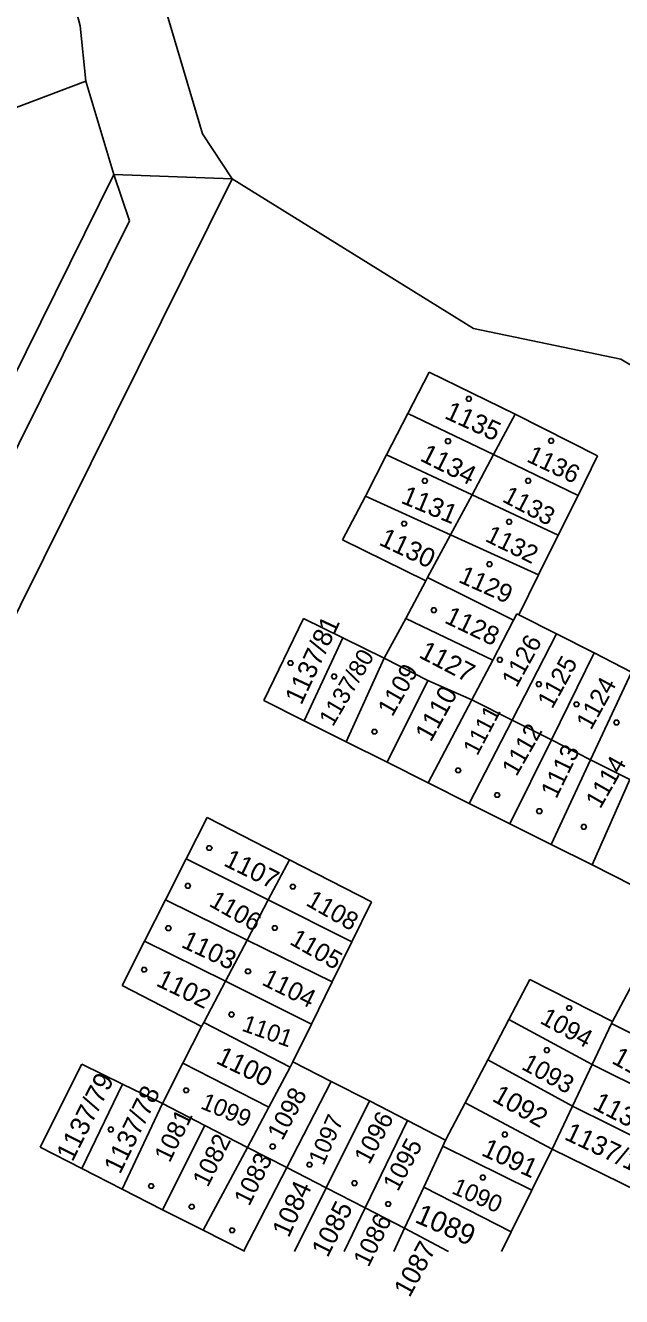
# Model space of a CAD drawing. Extents: x -621797 to -620972, y -1175539 to -1174697.
# Drawn here: x -621447.7 to -621408.1, y -1175535.9 to -1175451.4 of the extents above; entities that cross this region are included whole.
import ezdxf

# ---------------------------------------------------------------- set-up
doc = ezdxf.new("R2010")
doc.units = 0
for name, color, linetype in [('Rozvod plynu EON', 7, 'Continuous'), ('SDEL EON - popis', 7, 'Continuous'), ('Silnoproud EON', 7, 'Continuous'), ('Silnoproud EON - popis', 7, 'Continuous')]:
    doc.layers.add(name, color=color, linetype=linetype)

msp = doc.modelspace()

# ---------------------------------------------------------------- linework, layer by layer
at = {"layer": 'Rozvod plynu EON'}
for points in [[(-621418.2, -1175476.07), (-621418.11, -1175476.22), (-621418.2, -1175476.37), (-621418.38, -1175476.37), (-621418.47, -1175476.22), (-621418.38, -1175476.07)], [(-621419.58, -1175478.88), (-621419.49, -1175479.03), (-621419.58, -1175479.18), (-621419.76, -1175479.18), (-621419.85, -1175479.03), (-621419.76, -1175478.88)], [(-621412.73, -1175478.86), (-621412.64, -1175479.01), (-621412.73, -1175479.16), (-621412.91, -1175479.16), (-621413, -1175479.01), (-621412.91, -1175478.86)], [(-621421.12, -1175481.52), (-621421.03, -1175481.67), (-621421.12, -1175481.82), (-621421.3, -1175481.82), (-621421.39, -1175481.67), (-621421.3, -1175481.52)], [(-621414.26, -1175481.52), (-621414.17, -1175481.67), (-621414.26, -1175481.82), (-621414.44, -1175481.82), (-621414.53, -1175481.67), (-621414.44, -1175481.52)], [(-621415.52, -1175484.24), (-621415.43, -1175484.39), (-621415.52, -1175484.54), (-621415.7, -1175484.54), (-621415.79, -1175484.39), (-621415.7, -1175484.24)], [(-621422.5, -1175484.36), (-621422.41, -1175484.51), (-621422.5, -1175484.66), (-621422.68, -1175484.66), (-621422.77, -1175484.51), (-621422.68, -1175484.36)], [(-621416.83, -1175487.06), (-621416.74, -1175487.21), (-621416.83, -1175487.36), (-621417.01, -1175487.36), (-621417.1, -1175487.21), (-621417.01, -1175487.06)], [(-621420.52, -1175490.11), (-621420.43, -1175490.26), (-621420.52, -1175490.41), (-621420.7, -1175490.41), (-621420.79, -1175490.26), (-621420.7, -1175490.11)], [(-621430.04, -1175493.62), (-621429.95, -1175493.77), (-621430.04, -1175493.92), (-621430.22, -1175493.92), (-621430.31, -1175493.77), (-621430.22, -1175493.62)], [(-621416.13, -1175493.41), (-621416.04, -1175493.56), (-621416.13, -1175493.71), (-621416.31, -1175493.71), (-621416.4, -1175493.56), (-621416.31, -1175493.41)], [(-621427.15, -1175494.52), (-621427.06, -1175494.67), (-621427.15, -1175494.82), (-621427.33, -1175494.82), (-621427.42, -1175494.67), (-621427.33, -1175494.52)], [(-621413.55, -1175495.03), (-621413.46, -1175495.18), (-621413.55, -1175495.33), (-621413.73, -1175495.33), (-621413.82, -1175495.18), (-621413.73, -1175495.03)], [(-621411.04, -1175496.36), (-621410.95, -1175496.51), (-621411.04, -1175496.66), (-621411.22, -1175496.66), (-621411.31, -1175496.51), (-621411.22, -1175496.36)], [(-621408.39, -1175497.57), (-621408.3, -1175497.72), (-621408.39, -1175497.87), (-621408.57, -1175497.87), (-621408.66, -1175497.72), (-621408.57, -1175497.57)], [(-621424.47, -1175498.18), (-621424.38, -1175498.33), (-621424.47, -1175498.48), (-621424.65, -1175498.48), (-621424.74, -1175498.33), (-621424.65, -1175498.18)], [(-621418.9, -1175500.75), (-621418.81, -1175500.9), (-621418.9, -1175501.05), (-621419.08, -1175501.05), (-621419.17, -1175500.9), (-621419.08, -1175500.75)], [(-621416.31, -1175502.39), (-621416.22, -1175502.54), (-621416.31, -1175502.69), (-621416.49, -1175502.69), (-621416.58, -1175502.54), (-621416.49, -1175502.39)], [(-621413.51, -1175503.46), (-621413.42, -1175503.61), (-621413.51, -1175503.76), (-621413.69, -1175503.76), (-621413.78, -1175503.61), (-621413.69, -1175503.46)], [(-621410.56, -1175504.5), (-621410.47, -1175504.65), (-621410.56, -1175504.8), (-621410.74, -1175504.8), (-621410.83, -1175504.65), (-621410.74, -1175504.5)], [(-621435.44, -1175505.91), (-621435.35, -1175506.06), (-621435.44, -1175506.21), (-621435.62, -1175506.21), (-621435.71, -1175506.06), (-621435.62, -1175505.91)], [(-621436.86, -1175508.42), (-621436.77, -1175508.57), (-621436.86, -1175508.72), (-621437.04, -1175508.72), (-621437.13, -1175508.57), (-621437.04, -1175508.42)], [(-621429.89, -1175508.47), (-621429.8, -1175508.62), (-621429.89, -1175508.77), (-621430.07, -1175508.77), (-621430.16, -1175508.62), (-621430.07, -1175508.47)], [(-621438.16, -1175511.23), (-621438.07, -1175511.38), (-621438.16, -1175511.53), (-621438.34, -1175511.53), (-621438.43, -1175511.38), (-621438.34, -1175511.23)], [(-621431.09, -1175511.22), (-621431, -1175511.37), (-621431.09, -1175511.52), (-621431.27, -1175511.52), (-621431.36, -1175511.37), (-621431.27, -1175511.22)], [(-621439.77, -1175513.99), (-621439.68, -1175514.14), (-621439.77, -1175514.29), (-621439.95, -1175514.29), (-621440.04, -1175514.14), (-621439.95, -1175513.99)], [(-621432.87, -1175514.1), (-621432.78, -1175514.25), (-621432.87, -1175514.4), (-621433.05, -1175514.4), (-621433.14, -1175514.25), (-621433.05, -1175514.1)], [(-621433.96, -1175516.96), (-621433.87, -1175517.11), (-621433.96, -1175517.26), (-621434.14, -1175517.26), (-621434.23, -1175517.11), (-621434.14, -1175516.96)], [(-621411.52, -1175516.53), (-621411.43, -1175516.68), (-621411.52, -1175516.83), (-621411.7, -1175516.83), (-621411.79, -1175516.68), (-621411.7, -1175516.53)], [(-621413.01, -1175519.33), (-621412.92, -1175519.48), (-621413.01, -1175519.63), (-621413.19, -1175519.63), (-621413.28, -1175519.48), (-621413.19, -1175519.33)], [(-621436.98, -1175522), (-621436.89, -1175522.15), (-621436.98, -1175522.3), (-621437.16, -1175522.3), (-621437.25, -1175522.15), (-621437.16, -1175522)], [(-621441.99, -1175524.61), (-621441.9, -1175524.76), (-621441.99, -1175524.91), (-621442.17, -1175524.91), (-621442.26, -1175524.76), (-621442.17, -1175524.61)], [(-621415.81, -1175524.93), (-621415.72, -1175525.08), (-621415.81, -1175525.23), (-621415.99, -1175525.23), (-621416.08, -1175525.08), (-621415.99, -1175524.93)], [(-621431.23, -1175525.73), (-621431.14, -1175525.88), (-621431.23, -1175526.03), (-621431.41, -1175526.03), (-621431.5, -1175525.88), (-621431.41, -1175525.73)], [(-621428.78, -1175526.94), (-621428.69, -1175527.09), (-621428.78, -1175527.24), (-621428.96, -1175527.24), (-621429.05, -1175527.09), (-621428.96, -1175526.94)], [(-621425.8, -1175528.17), (-621425.71, -1175528.32), (-621425.8, -1175528.47), (-621425.98, -1175528.47), (-621426.07, -1175528.32), (-621425.98, -1175528.17)], [(-621417.26, -1175527.79), (-621417.17, -1175527.94), (-621417.26, -1175528.09), (-621417.44, -1175528.09), (-621417.53, -1175527.94), (-621417.44, -1175527.79)], [(-621439.3, -1175528.36), (-621439.21, -1175528.51), (-621439.3, -1175528.66), (-621439.48, -1175528.66), (-621439.57, -1175528.51), (-621439.48, -1175528.36)], [(-621436.61, -1175529.73), (-621436.52, -1175529.88), (-621436.61, -1175530.03), (-621436.79, -1175530.03), (-621436.88, -1175529.88), (-621436.79, -1175529.73)], [(-621423.55, -1175529.55), (-621423.46, -1175529.7), (-621423.55, -1175529.85), (-621423.73, -1175529.85), (-621423.82, -1175529.7), (-621423.73, -1175529.55)], [(-621433.92, -1175531.3), (-621433.83, -1175531.45), (-621433.92, -1175531.6), (-621434.1, -1175531.6), (-621434.19, -1175531.45), (-621434.1, -1175531.3)]]:
    msp.add_lwpolyline(points, close=True, dxfattribs=at)
at = {"layer": 'SDEL EON - popis'}
for p, q in [((-621440.83, -1175464.39), (-621441.87, -1175461.33)), ((-621474.84, -1175532.85), (-621440.83, -1175464.39))]:
    msp.add_line(p, q, dxfattribs=at)
at = {"layer": 'Silnoproud EON'}
for p, q in [((-621441.44, -1175440.21), (-621435.99, -1175458.63)), ((-621444.1, -1175451.45), (-621446.68, -1175441.99)), ((-621443.74, -1175455.13), (-621444.1, -1175451.45)), ((-621462.68, -1175462.26), (-621443.74, -1175455.13)), ((-621443.74, -1175455.13), (-621441.87, -1175461.33)), ((-621435.99, -1175458.63), (-621434.02, -1175461.6)), ((-621449.7, -1175477.12), (-621441.87, -1175461.33)), ((-621441.87, -1175461.33), (-621434.02, -1175461.6)), ((-621434.02, -1175461.6), (-621469.406, -1175532.85)), ((-621417.98, -1175471.56), (-621434.02, -1175461.6)), ((-621408.19, -1175473.58), (-621417.98, -1175471.56)), ((-621399.98, -1175478.5), (-621408.19, -1175473.58)), ((-621422.33, -1175477.19), (-621420.91, -1175474.45)), ((-621420.91, -1175474.45), (-621415.2, -1175477.25)), ((-621423.75, -1175479.94), (-621422.33, -1175477.19)), ((-621422.33, -1175477.19), (-621416.64, -1175479.93)), ((-621415.2, -1175477.25), (-621416.64, -1175479.93)), ((-621415.2, -1175477.25), (-621409.73, -1175480)), ((-621425.16, -1175482.68), (-621423.75, -1175479.94)), ((-621423.75, -1175479.94), (-621418.07, -1175482.6)), ((-621416.64, -1175479.93), (-621418.07, -1175482.6)), ((-621416.64, -1175479.93), (-621411.03, -1175482.64)), ((-621409.73, -1175480), (-621411.03, -1175482.64)), ((-621418.07, -1175482.6), (-621419.5, -1175485.26)), ((-621418.07, -1175482.6), (-621412.34, -1175485.28)), ((-621411.03, -1175482.64), (-621412.34, -1175485.28)), ((-621426.67, -1175485.59), (-621425.16, -1175482.68)), ((-621425.16, -1175482.68), (-621419.5, -1175485.26)), ((-621421.14, -1175488.3), (-621426.67, -1175485.59)), ((-621419.5, -1175485.26), (-621421.03, -1175488.1)), ((-621419.5, -1175485.26), (-621413.65, -1175487.92)), ((-621412.34, -1175485.28), (-621413.65, -1175487.92)), ((-621422.48, -1175490.81), (-621421.14, -1175488.3)), ((-621421.03, -1175488.1), (-621421.14, -1175488.3)), ((-621421.03, -1175488.1), (-621415.31, -1175490.92)), ((-621413.65, -1175487.92), (-621414.96, -1175490.57)), ((-621431.91, -1175496.26), (-621429.26, -1175490.82)), ((-621429.26, -1175490.82), (-621426.66, -1175492.1)), ((-621423.9, -1175493.45), (-621422.48, -1175490.81)), ((-621422.48, -1175490.81), (-621416.7, -1175493.57)), ((-621415.31, -1175490.92), (-621416.7, -1175493.57)), ((-621415.09, -1175490.5), (-621415.31, -1175490.92)), ((-621414.96, -1175490.57), (-621415.09, -1175490.5)), ((-621414.96, -1175490.57), (-621412.46, -1175491.84)), ((-621412.46, -1175491.84), (-621415.41, -1175497.56)), ((-621412.46, -1175491.84), (-621409.96, -1175493.1)), ((-621426.66, -1175492.1), (-621429.22, -1175497.61)), ((-621426.66, -1175492.1), (-621423.9, -1175493.45)), ((-621423.9, -1175493.45), (-621426.44, -1175499)), ((-621423.9, -1175493.45), (-621421.01, -1175494.94)), ((-621416.7, -1175493.57), (-621418.09, -1175496.21)), ((-621409.96, -1175493.1), (-621412.8, -1175498.87)), ((-621409.96, -1175493.1), (-621407.47, -1175494.37)), ((-621407.47, -1175494.37), (-621410.19, -1175500.19)), ((-621421.01, -1175494.94), (-621423.72, -1175500.36)), ((-621421.01, -1175494.94), (-621418.09, -1175496.21)), ((-621429.22, -1175497.61), (-621431.91, -1175496.26)), ((-621418.09, -1175496.21), (-621420.99, -1175501.73)), ((-621418.09, -1175496.21), (-621415.41, -1175497.56)), ((-621426.44, -1175499), (-621429.22, -1175497.61)), ((-621415.41, -1175497.56), (-621418.26, -1175503.09)), ((-621415.41, -1175497.56), (-621412.8, -1175498.87)), ((-621423.72, -1175500.36), (-621426.44, -1175499)), ((-621412.8, -1175498.87), (-621415.55, -1175504.45)), ((-621412.8, -1175498.87), (-621410.19, -1175500.19)), ((-621420.99, -1175501.73), (-621423.72, -1175500.36)), ((-621410.19, -1175500.19), (-621412.82, -1175505.82)), ((-621410.19, -1175500.19), (-621407.58, -1175501.5)), ((-621418.26, -1175503.09), (-621420.99, -1175501.73)), ((-621407.58, -1175501.5), (-621410.1, -1175507.18)), ((-621415.55, -1175504.45), (-621418.26, -1175503.09)), ((-621435.68, -1175504.03), (-621437.07, -1175506.77)), ((-621430.21, -1175506.84), (-621435.68, -1175504.03)), ((-621412.82, -1175505.82), (-621415.55, -1175504.45)), ((-621410.1, -1175507.18), (-621412.82, -1175505.82)), ((-621437.07, -1175506.77), (-621438.45, -1175509.5)), ((-621437.07, -1175506.77), (-621431.61, -1175509.51)), ((-621430.21, -1175506.84), (-621431.61, -1175509.51)), ((-621424.75, -1175509.64), (-621430.21, -1175506.84)), ((-621407.39, -1175508.54), (-621410.1, -1175507.18)), ((-621438.45, -1175509.5), (-621439.83, -1175512.24)), ((-621438.45, -1175509.5), (-621433.01, -1175512.17)), ((-621431.61, -1175509.51), (-621433.01, -1175512.17)), ((-621431.61, -1175509.51), (-621426.06, -1175512.3)), ((-621426.06, -1175512.3), (-621424.75, -1175509.64)), ((-621433.01, -1175512.17), (-621434.46, -1175514.91)), ((-621433.01, -1175512.17), (-621427.36, -1175514.95)), ((-621439.83, -1175512.24), (-621441.33, -1175515.19)), ((-621439.83, -1175512.24), (-621434.46, -1175514.91)), ((-621427.36, -1175514.95), (-621426.06, -1175512.3)), ((-621441.33, -1175515.19), (-621436.04, -1175517.92)), ((-621434.46, -1175514.91), (-621435.9, -1175517.65)), ((-621434.46, -1175514.91), (-621428.74, -1175517.76)), ((-621428.74, -1175517.76), (-621427.36, -1175514.95)), ((-621414.23, -1175514.78), (-621415.63, -1175517.45)), ((-621408.74, -1175517.59), (-621414.23, -1175514.78)), ((-621407.44, -1175515.12), (-621408.74, -1175517.59)), ((-621436.04, -1175517.92), (-621437.28, -1175520.35)), ((-621435.9, -1175517.65), (-621436.04, -1175517.92)), ((-621435.9, -1175517.65), (-621430.16, -1175520.61)), ((-621429.97, -1175520.25), (-621428.74, -1175517.76)), ((-621415.63, -1175517.45), (-621417.03, -1175520.13)), ((-621415.63, -1175517.45), (-621410.09, -1175520.44)), ((-621410.09, -1175520.44), (-621408.8, -1175517.71)), ((-621408.8, -1175517.71), (-621408.74, -1175517.59)), ((-621408.8, -1175517.71), (-621402.93, -1175520.64)), ((-621444.01, -1175520.42), (-621446.77, -1175525.93)), ((-621441.29, -1175521.74), (-621444.01, -1175520.42)), ((-621437.28, -1175520.35), (-621438.65, -1175523.02)), ((-621437.28, -1175520.35), (-621431.58, -1175523.28)), ((-621430.16, -1175520.61), (-621431.58, -1175523.28)), ((-621429.97, -1175520.25), (-621430.16, -1175520.61)), ((-621427.43, -1175521.56), (-621429.97, -1175520.25)), ((-621417.03, -1175520.13), (-621418.52, -1175522.99)), ((-621417.03, -1175520.13), (-621411.4, -1175523.2)), ((-621411.4, -1175523.2), (-621410.09, -1175520.44)), ((-621410.09, -1175520.44), (-621404.29, -1175523.33)), ((-621441.29, -1175521.74), (-621443.99, -1175527.35)), ((-621438.65, -1175523.02), (-621441.29, -1175521.74)), ((-621427.43, -1175521.56), (-621430.38, -1175527.28)), ((-621424.89, -1175522.86), (-621427.43, -1175521.56)), ((-621438.65, -1175523.02), (-621441.32, -1175528.71)), ((-621438.65, -1175523.02), (-621435.83, -1175524.49)), ((-621424.89, -1175522.86), (-621427.76, -1175528.62)), ((-621422.36, -1175524.16), (-621424.89, -1175522.86)), ((-621418.52, -1175522.99), (-621419.83, -1175525.46)), ((-621418.52, -1175522.99), (-621412.75, -1175526.06)), ((-621431.58, -1175523.28), (-621433, -1175525.94)), ((-621412.75, -1175526.06), (-621411.4, -1175523.2)), ((-621411.4, -1175523.2), (-621405.66, -1175526.06)), ((-621435.83, -1175524.49), (-621438.63, -1175530.08)), ((-621435.83, -1175524.49), (-621433, -1175525.94)), ((-621422.36, -1175524.16), (-621425.17, -1175529.96)), ((-621419.83, -1175525.46), (-621422.36, -1175524.16)), ((-621419.83, -1175525.46), (-621420.01, -1175525.86)), ((-621446.77, -1175525.93), (-621443.99, -1175527.35)), ((-621433, -1175525.94), (-621435.93, -1175531.45)), ((-621433, -1175525.94), (-621430.38, -1175527.28)), ((-621420.01, -1175525.86), (-621421.28, -1175528.58)), ((-621420.01, -1175525.86), (-621414.1, -1175528.78)), ((-621414.1, -1175528.78), (-621412.75, -1175526.06)), ((-621412.75, -1175526.06), (-621407.06, -1175528.85)), ((-621443.99, -1175527.35), (-621441.32, -1175528.71)), ((-621430.38, -1175527.28), (-621433.24, -1175532.82)), ((-621430.38, -1175527.28), (-621427.76, -1175528.62)), ((-621441.32, -1175528.71), (-621438.63, -1175530.08)), ((-621427.76, -1175528.62), (-621429.867, -1175532.85)), ((-621427.76, -1175528.62), (-621425.17, -1175529.96)), ((-621421.28, -1175528.58), (-621422.55, -1175531.3)), ((-621421.28, -1175528.58), (-621415.48, -1175531.56)), ((-621415.48, -1175531.56), (-621414.1, -1175528.78)), ((-621438.63, -1175530.08), (-621435.93, -1175531.45)), ((-621425.17, -1175529.96), (-621426.571, -1175532.85)), ((-621425.17, -1175529.96), (-621422.55, -1175531.3)), ((-621435.93, -1175531.45), (-621433.24, -1175532.82)), ((-621422.55, -1175531.3), (-621423.274, -1175532.85)), ((-621422.55, -1175531.3), (-621419.72, -1175532.81)), ((-621416.122, -1175532.85), (-621415.48, -1175531.56)), ((-621433.24, -1175532.82), (-621433.181, -1175532.85)), ((-621419.72, -1175532.81), (-621419.74, -1175532.85)), ((-621419.72, -1175532.81), (-621419.646, -1175532.85))]:
    msp.add_line(p, q, dxfattribs=at)

# ---------------------------------------------------------------- texts
at = {"layer": 'Silnoproud EON - popis'}
for s, height, rotation, p in [('1135', 1.27, 335.2949, (-621419.973, -1175477.483)), ('1134', 1.27, 333.34684, (-621421.598, -1175480.292)), ('1136', 1.2, 334.77924, (-621414.509, -1175480.358)), ('1131', 1.27, 337.41484, (-621422.869, -1175483.113)), ('1133', 1.2, 332.08634, (-621416.135, -1175483.01)), ('1130', 1.27, 334.49276, (-621424.325, -1175485.886)), ('1132', 1.2, 333.9198, (-621417.271, -1175485.642)), ('1129', 1.22, 336.03975, (-621419.045, -1175488.371)), ('1128', 1.24, 334.37817, (-621419.972, -1175491.066)), ('1137/81', 1.27, 64.97341, (-621429.416, -1175496.614)), ('1126', 1.2, 61.19189, (-621415.116, -1175495.457)), ('1127', 1.27, 332.43011, (-621421.672, -1175493.365)), ('1137/80', 1.14, 59.58761, (-621427.321, -1175498.048)), ('1125', 1.2, 61.19189, (-621412.746, -1175496.867)), ('1109', 1.2, 60.27516, (-621423.373, -1175497.389)), ('1124', 1.2, 61.19189, (-621410.166, -1175498.277)), ('1110', 1.27, 61.1346, (-621420.816, -1175499.074)), ('1111', 1.14, 62.16592, (-621417.722, -1175499.982)), ('1112', 1.2, 60.27516, (-621415.123, -1175501.359)), ('1113', 1.22, 64.05668, (-621412.469, -1175502.838)), ('1114', 1.2, 60.27516, (-621409.553, -1175503.509)), ('1107', 1.25, 333.9771, (-621434.648, -1175507.196)), ('1106', 1.2, 330.31017, (-621435.619, -1175509.867)), ('1108', 1.2, 330.31017, (-621429.179, -1175509.827)), ('1103', 1.24, 334.83654, (-621437.461, -1175512.611)), ('1105', 1.2, 330.31017, (-621430.259, -1175512.407)), ('1102', 1.24, 334.20628, (-621439.135, -1175515.17)), ('1104', 1.22, 333.63333, (-621432.109, -1175515.111)), ('1101', 1.14, 340.45152, (-621433.438, -1175518.175)), ('1094', 1.2, 331.2269, (-621413.627, -1175517.653)), ('1100', 1.27, 334.14899, (-621435.155, -1175520.318)), ('1137/13', 1.27, 331.34149, (-621408.863, -1175520.311)), ('1093', 1.2, 331.2269, (-621414.857, -1175520.703)), ('1137/79', 1.28, 63.19724, (-621444.62, -1175526.95)), ('1137/78', 1.27, 63.99939, (-621441.461, -1175527.776)), ('1098', 1.2, 62.10862, (-621430.68, -1175525.545)), ('1092', 1.27, 330.53935, (-621416.808, -1175522.82)), ('1099', 1.14, 337.35755, (-621436.177, -1175523.331)), ('1137/14', 1.27, 332.77389, (-621410.129, -1175523.344)), ('1081', 1.2, 63.88479, (-621438.168, -1175527.011)), ('1097', 1.14, 66.17663, (-621427.948, -1175527.2)), ('1096', 1.2, 62.10862, (-621424.91, -1175527.135)), ('1137/15', 1.27, 334.66465, (-621412.007, -1175525.376)), ('1082', 1.2, 63.88479, (-621435.628, -1175528.651)), ('1095', 1.2, 62.10862, (-621423, -1175528.925)), ('1091', 1.27, 335.46679, (-621417.523, -1175526.442)), ('1083', 1.2, 63.88479, (-621432.878, -1175529.901)), ('1084', 1.27, 65.54637, (-621430.256, -1175531.997)), ('1090', 1.14, 336.38352, (-621419.493, -1175528.969)), ('1085', 1.27, 62.96806, (-621427.673, -1175533.314)), ('1089', 1.36, 336.38352, (-621421.942, -1175530.887)), ('1086', 1.2, 63.88479, (-621424.948, -1175533.951)), ('1087', 1.27, 61.42108, (-621422.225, -1175535.965))]:
    msp.add_text(s, height=height, rotation=rotation, dxfattribs=at).set_placement(p)

doc.saveas('drawing.dxf')
